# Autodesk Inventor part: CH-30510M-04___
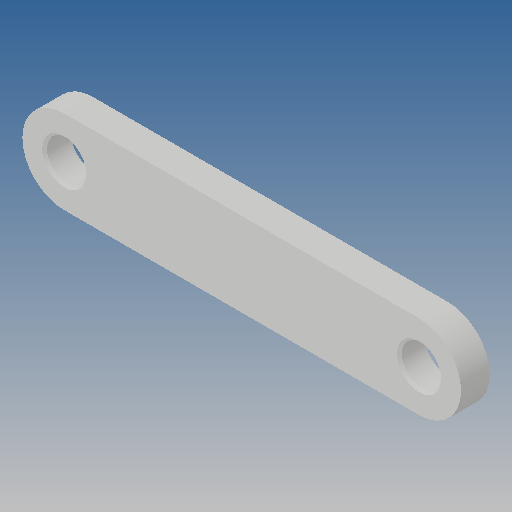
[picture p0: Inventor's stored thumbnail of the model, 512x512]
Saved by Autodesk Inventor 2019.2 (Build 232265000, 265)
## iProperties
Created: 2010-06
Part Number: CH-30510M-04___
Material: Ogólny
Document SubType Name: Modeling
Designer: CADENGINEERING4
Density: 1 g/cm^3
Appearance: Domyślna
Author: CADENGINEERING4
Revision Number: ANY
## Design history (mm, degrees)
feature "NONE"
node "Bryła1"
